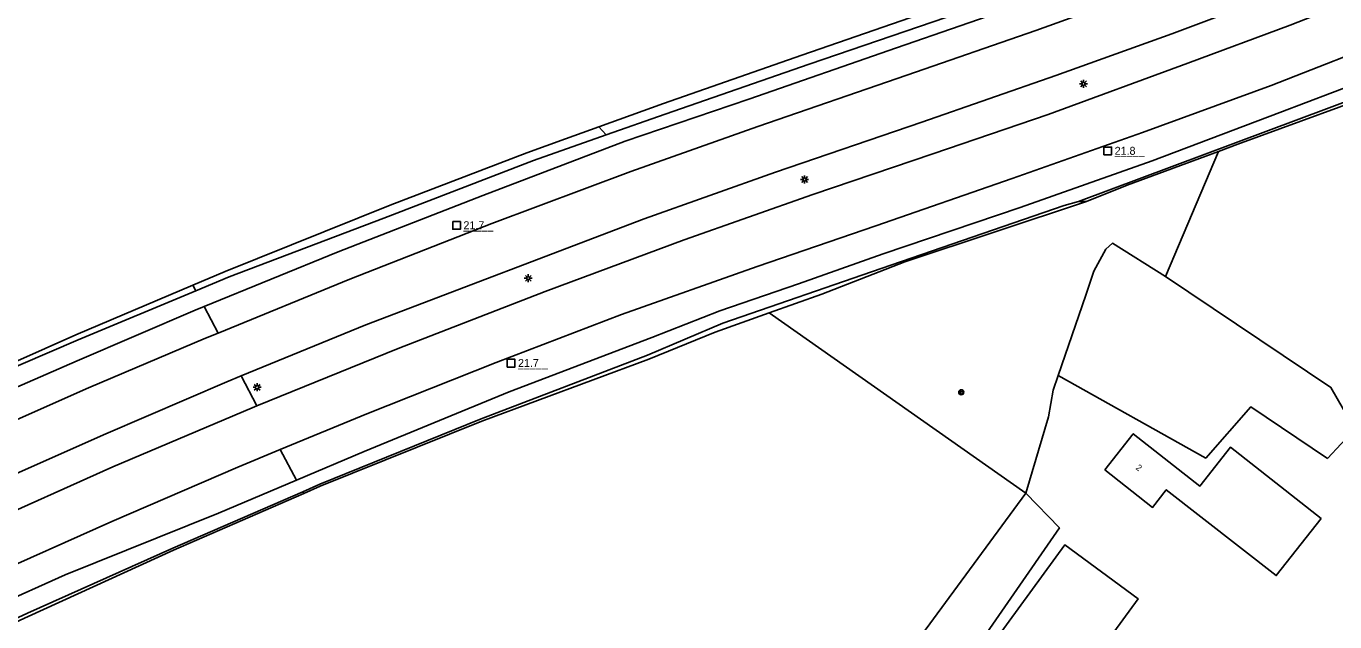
# Model space of a CAD drawing. Extents: x 124000 to 129000, y 395500 to 397503.
# Drawn here: x 125164.9 to 125369.3, y 397157 to 397250 of the extents above; entities that cross this region are included whole.
import ezdxf

# ---------------------------------------------------------------- set-up
doc = ezdxf.new("R2010")
doc.units = 0
for name, color, linetype in [('gg-afsc-erfafscheiding', 7, 'Continuous'), ('gg-anno-huisnummerreeks BGT', 7, 'Continuous'), ('gg-bbg-bijgebouw', 7, 'Continuous'), ('gg-bbg-gedigitaliseerde bebouwing', 7, 'Continuous'), ('gg-bbg-hoofdgebouw', 7, 'Continuous'), ('gg-knt-bronhoudergrens', 7, 'Continuous'), ('gg-knt-verharding', 7, 'Continuous'), ('gg-kntw-bovenkant insteek waterloop', 7, 'Continuous'), ('gt-anno-nummer hm paal', 7, 'Continuous'), ('gt-grn-groengrens', 7, 'Continuous'), ('gt-symb-boom', 7, 'Continuous'), ('gt-symb-hm paal', 7, 'Continuous'), ('gt-symb-lichtmast', 7, 'Continuous'), ('gx-grn-maaiveld', 7, 'Continuous')]:
    doc.layers.add(name, color=color, linetype=linetype)

# ---------------------------------------------------------------- blocks, each defined once
blk = doc.blocks.new('gt0-LMAST')
at = {"layer": 'gt-symb-lichtmast'}
for p, q in [((-0.18, 0.17), (-0.45, 0.44)), ((-0.01, 0.25), (-0.01, 0.62)), ((0.17, 0.17), (0.44, 0.44)), ((-0.26, 0), (-0.63, 0)), ((-0.18, -0.18), (-0.45, -0.45)), ((-0.01, -0.25), (-0.01, -0.63)), ((0.44, -0.45), (0.17, -0.18)), ((0.24, 0), (0.62, 0))]:
    blk.add_line(p, q, dxfattribs=at)
blk.add_circle((-0.01, 0), 0.25, dxfattribs=at)
blk = doc.blocks.new('gt0-HMpaal')
at = {"layer": 'gt-symb-hm paal'}
blk.add_lwpolyline([(-0.6, 0.6), (0.6, 0.6), (0.6, -0.6), (-0.6, -0.6)], close=True, dxfattribs=at)
blk = doc.blocks.new('gt0-BOOM')
at = {"layer": 'gt-symb-boom'}
for radius in [0.4, 0.2]:
    blk.add_circle((0, 0), radius, dxfattribs=at)

msp = doc.modelspace()

# ---------------------------------------------------------------- linework, layer by layer
at = {"layer": 'gg-afsc-erfafscheiding'}
for points in [[(125394.47, 397246.59), (125379.86, 397240.99), (125354.19, 397231.61), (125351.13, 397230.48)], [(125351.13, 397230.48), (125336.9, 397225.2), (125330.55, 397222.67)], [(125330.55, 397222.67), (125302.15, 397213.22), (125289.21, 397208.18), (125280.94, 397205.23)], [(125280.94, 397205.23), (125272.52, 397202.23), (125262.17, 397198.01)], [(125208.25, 397177.01), (125210.85, 397178.14), (125236.06, 397188.33), (125262.17, 397198.01)], [(125001.84, 397070.77), (125020.74, 397082.7), (125060.32, 397105.39), (125080.15, 397116.03), (125099.94, 397126.54), (125120.15, 397136.63), (125142.45, 397147.32), (125165.23, 397157.78), (125187.91, 397168.16), (125208.25, 397177.01)]]:
    msp.add_lwpolyline(points, dxfattribs=at)
at = {"layer": 'gg-bbg-bijgebouw'}
msp.add_lwpolyline([(125306.12, 397140.14), (125317.64, 397131.79), (125338.58, 397160.55), (125327.12, 397168.98), (125306.12, 397140.14)], dxfattribs=at)
at = {"layer": 'gg-bbg-gedigitaliseerde bebouwing'}
msp.add_lwpolyline([(125333.38, 397180.69), (125337.82, 397186.34), (125348.24, 397178.16), (125353.01, 397184.24), (125367.19, 397173.13)], dxfattribs=at)
at = {"layer": 'gg-bbg-hoofdgebouw'}
msp.add_lwpolyline([(125333.38, 397180.69), (125340.84, 397174.84), (125343, 397177.61), (125360.18, 397164.18), (125367.19, 397173.13)], dxfattribs=at)
at = {"layer": 'gg-knt-bronhoudergrens'}
for p, q in [((125351.13, 397230.48), (125342.89, 397210.91)), ((125321.05, 397177.08), (125280.94, 397205.23)), ((125324.57, 397188.99), (125321.05, 397177.08)), ((125298.32, 397146.1), (125321.05, 397177.08))]:
    msp.add_line(p, q, dxfattribs=at)
for points in [[(125326.1, 397195.46), (125330.4, 397208.01), (125331.7, 397211.76), (125333.57, 397215.18), (125334.59, 397216.12), (125342.89, 397210.91)], [(125342.89, 397210.91), (125368.71, 397193.59), (125372.42, 397187.08), (125368.18, 397182.49)], [(125324.57, 397188.99), (125325.32, 397193.17), (125326.1, 397195.46)], [(125368.18, 397182.49), (125356.22, 397190.56), (125349.16, 397182.55), (125326.1, 397195.46)], [(125303.99, 397139.35), (125326.29, 397171.62), (125321.05, 397177.08)]]:
    msp.add_lwpolyline(points, dxfattribs=at)
at = {"layer": 'gg-knt-verharding'}
for points in [[(125573.94, 397357.46), (125556.13, 397347.16), (125534.72, 397335.38), (125512.12, 397323.32), (125490.61, 397312.41), (125467.71, 397301.33), (125445.04, 397290.75), (125422.65, 397280.78), (125402.74, 397272.26), (125381.07, 397263.36), (125360.35, 397255.08), (125343.85, 397248.87), (125325.72, 397242.33), (125304.81, 397235.06), (125281.95, 397227.25), (125261.44, 397219.96), (125217.98, 397203.36), (125198.47, 397195.39)], [(125456.1, 397304.32), (125437.1, 397295.54), (125414.44, 397285.54), (125393.38, 397276.62), (125371.97, 397267.93), (125354.72, 397261.22), (125342.59, 397256.63), (125322.62, 397249.35), (125302.48, 397242.4), (125279.19, 397234.39), (125259.36, 397227.31), (125237.65, 397219.23), (125215.48, 397210.51), (125194.89, 397202.09)], [(125200.95, 397190.72), (125223, 397199.67), (125245.97, 397208.57), (125267.66, 397216.65), (125287.79, 397223.72), (125306.52, 397230.07), (125324.52, 397236.22), (125346.34, 397244.25), (125362.35, 397250.19), (125383.39, 397258.5), (125404.75, 397267.29), (125420.35, 397273.93)], [(125423.85, 397267.02), (125422.2, 397266.28), (125400.3, 397257.16), (125379.32, 397248.61), (125359.35, 397240.79), (125339.27, 397233.44), (125318.9, 397226.22), (125297.64, 397218.86), (125279.07, 397212.51), (125257.89, 397204.99), (125238.32, 397197.47), (125218.11, 397189.46), (125204.59, 397183.88)], [(125194.89, 397202.09), (125192.9, 397201.28), (125174.66, 397193.51), (125154.05, 397184.42), (125133.52, 397174.96), (125111.34, 397164.23), (125091.94, 397154.63), (125072.1, 397144.23), (125055.92, 397135.43), (125036.39, 397124.64), (125016.69, 397113.37), (124995.91, 397101.03), (124988.32, 397096.18), (124971.92, 397085.18), (124956.01, 397073.42), (124938.33, 397059.27), (124922.1, 397044.69), (124908.71, 397031.79), (124899.79, 397022.66), (124888.93, 397010.49)], [(125198.47, 397195.39), (125196.25, 397194.48), (125177.36, 397186.33), (125157.23, 397177.43)], [(124844.55, 396919.9), (124851.56, 396933.09), (124860.89, 396948.99), (124872.93, 396967.43), (124886.49, 396986), (124900.04, 397002.62), (124914.34, 397018.39), (124929.47, 397033.78), (124945.2, 397048.09), (124962.23, 397062.03), (124980.25, 397075.52), (124999.09, 397088.08), (125016.82, 397098.71), (125038.01, 397110.9), (125057.64, 397121.88), (125077.17, 397132.43), (125096.81, 397142.56), (125115.47, 397151.93), (125136.66, 397162.15), (125157.49, 397171.8), (125178.45, 397181.16), (125200.22, 397190.42), (125200.95, 397190.72)], [(125204.59, 397183.88), (125197.96, 397181.14), (125178.29, 397172.64), (125158.21, 397163.65), (125138.37, 397154.47), (125120.35, 397145.72), (125101.02, 397136.08), (125082.34, 397126.43), (125064.11, 397116.61)]]:
    msp.add_lwpolyline(points, dxfattribs=at)
at = {"layer": 'gg-kntw-bovenkant insteek waterloop'}
msp.add_line((125327.06, 397222), (125329.3, 397222.63), dxfattribs=at)
for points in [[(125539.23, 397317.94), (125527.89, 397311.48), (125511.01, 397302.84), (125489.62, 397292.32), (125469.13, 397282.43), (125447.03, 397272.28), (125424.39, 397262.32), (125401.77, 397252.72), (125381.29, 397244.39), (125360.75, 397236.55), (125340.81, 397229.01), (125320.17, 397221.71), (125298.76, 397214.49), (125285.55, 397209.76), (125273.27, 397205.54), (125262.61, 397201.4), (125240.33, 397192.92), (125217.68, 397183.58), (125207.14, 397179.11)], [(125192.7, 397206.22), (125213.66, 397214.8), (125236.26, 397223.58), (125258.45, 397232.05), (125277.76, 397238.66), (125300.87, 397246.68), (125320.75, 397253.53), (125342.68, 397261.3)], [(125340.65, 397263.04), (125310.87, 397252.21), (125287.23, 397244.13), (125264.73, 397236.31), (125255.49, 397233.06)], [(125329.3, 397222.63), (125368.43, 397237.28), (125393.1, 397246.52)], [(125255.49, 397233.06), (125244.14, 397229.07), (125220.76, 397220.05), (125196.62, 397210.89), (125191.38, 397208.7)], [(125208.1, 397177.29), (125210.78, 397178.45), (125235.96, 397188.7), (125261.97, 397198.62), (125273.75, 397203.61), (125298.45, 397212.2), (125327.06, 397222)], [(125191.38, 397208.7), (125173.05, 397201.03), (125150.21, 397191.21), (125132.28, 397182.89), (125108.67, 397171.6), (125086.18, 397160.4), (125066.07, 397150.08), (125045.54, 397138.96), (125023.83, 397126.94), (125003.42, 397115), (125003.16, 397115.31)], [(125192.7, 397206.22), (125191.3, 397205.65), (125172.87, 397197.76), (125152.4, 397188.85), (125131.44, 397179.27), (125109.48, 397168.75), (125089.85, 397158.85), (125070.11, 397148.38), (125053.74, 397139.83), (125034.39, 397128.75), (125014.25, 397117.13), (125005.08, 397111.72), (125002.55, 397112.13), (125001.05, 397113.53)], [(125207.14, 397179.11), (125194.97, 397173.95), (125170.99, 397164.3), (125149.18, 397154.5), (125126.36, 397143.59), (125103.5, 397132.25), (125083.22, 397121.67), (125061.88, 397110.28), (125041.96, 397099.08), (125021.3, 397087.05), (124999.59, 397073.63), (124998.67, 397072.4), (124998.37, 397070.74), (124998.39, 397070.12)], [(125208.1, 397177.29), (125187.82, 397168.48), (125165.12, 397158.29), (125142.38, 397147.77), (125120.14, 397137.08), (125099.69, 397126.88), (125080.13, 397116.52), (125060.27, 397105.86), (125043.06, 397096.17), (125020.52, 397083.04), (125001.27, 397070.84), (125001.28, 397070.38)]]:
    msp.add_lwpolyline(points, dxfattribs=at)
at = {"layer": 'gt-grn-groengrens'}
for p, q in [((125329.3, 397222.63), (125330.55, 397222.67)), ((125190.92, 397209.56), (125191.38, 397208.7)), ((125192.7, 397206.22), (125194.89, 397202.09)), ((125200.95, 397190.72), (125198.47, 397195.39)), ((125204.59, 397183.88), (125207.14, 397179.11)), ((125208.1, 397177.29), (125208.25, 397177.01))]:
    msp.add_line(p, q, dxfattribs=at)
at = {"layer": 'gx-grn-maaiveld'}
for p, q in [((125249.13, 397232.42), (125254.33, 397234.31)), ((125254.33, 397234.31), (125255.49, 397233.06)), ((125195.97, 397211.7), (125190.92, 397209.56))]:
    msp.add_line(p, q, dxfattribs=at)
for points in [[(125254.33, 397234.31), (125264.47, 397237.98), (125286.08, 397245.54), (125310.04, 397253.82), (125341, 397264.95), (125341.41, 397265.3)], [(125249.13, 397232.42), (125243.13, 397230.25), (125221.78, 397222.05), (125195.97, 397211.7)], [(125004, 397115.79), (125023.49, 397127.21), (125045.5, 397139.53), (125065.56, 397150.3), (125085.78, 397160.61), (125108.19, 397171.97), (125132.12, 397183.54), (125149.6, 397191.54), (125172.64, 397201.81), (125190.92, 397209.56)]]:
    msp.add_lwpolyline(points, dxfattribs=at)

# ---------------------------------------------------------------- block references
at = {"layer": 'gt-symb-boom'}
msp.add_blockref('gt0-BOOM', (125310.97, 397192.83), dxfattribs=at)
at = {"layer": 'gt-symb-hm paal'}
for p in [(125333.85, 397230.55), (125232.13, 397218.91), (125240.65, 397197.38)]:
    msp.add_blockref('gt0-HMpaal', p, dxfattribs=at)
at = {"layer": 'gt-symb-lichtmast'}
for p in [(125330.07, 397241.04), (125286.51, 397226.09), (125243.33, 397210.66), (125200.99, 397193.62)]:
    msp.add_blockref('gt0-LMAST', p, dxfattribs=at)

# ---------------------------------------------------------------- texts
at = {"layer": 'gg-anno-huisnummerreeks BGT'}
msp.add_text('2', height=1, rotation=321.8, dxfattribs=at).set_placement((125338.13, 397180.89))
at = {"layer": 'gt-anno-nummer hm paal'}
for s, p in [('21.8', (125334.93, 397229.94)), ('21.7', (125233.21, 397218.31)), ('21.7', (125241.73, 397196.78))]:
    msp.add_text(s, height=1.25, dxfattribs=at).set_placement(p)
at = {"layer": 'gt-symb-hm paal'}
for p in [(125334.93, 397229.94), (125233.21, 397218.31), (125241.73, 397196.78)]:
    msp.add_text('_____', height=1.25, dxfattribs=at).set_placement(p)

doc.saveas('drawing.dxf')
